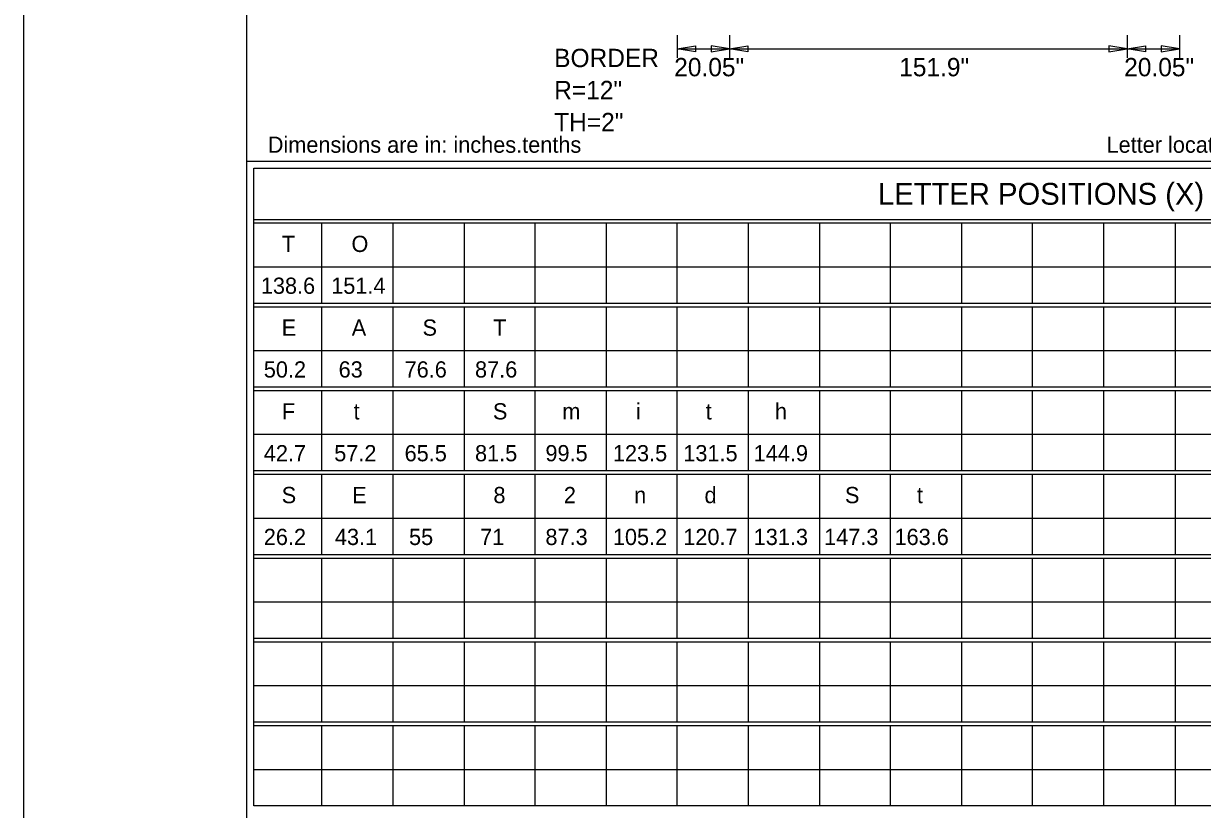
# Model space of a CAD drawing. Extents: x 2150010 to 2150174, y 145114 to 145224.
# Drawn here: x 2150010.46 to 2150048, y 145167.07 to 145192.08 of the extents above; entities that cross this region are included whole.
import ezdxf

# ---------------------------------------------------------------- set-up
doc = ezdxf.new("R2010")
doc.units = 0
for name, color, linetype in [('BORDER', 7, 'Continuous'), ('GSDIMS', 7, 'Continuous'), ('Level 1', 7, 'Continuous'), ('PDF', 7, 'Continuous')]:
    doc.layers.add(name, color=color, linetype=linetype)

msp = doc.modelspace()

# ---------------------------------------------------------------- linework, layer by layer
at = {"layer": 'BORDER'}
for p, q in [((2150010.458, 145219.948), (2150010.458, 145114.088)), ((2150017.557, 145216.512), (2150017.557, 145117.388))]:
    msp.add_line(p, q, dxfattribs=at)
at = {"layer": 'GSDIMS'}
for p, q in [((2150031.27, 145191.716), (2150031.27, 145190.986)), ((2150031.27, 145191.716), (2150031.27, 145190.986)), ((2150032.942, 145191.716), (2150032.942, 145190.986)), ((2150032.942, 145191.716), (2150032.942, 145190.986)), ((2150045.598, 145191.716), (2150045.598, 145190.986)), ((2150045.598, 145191.716), (2150045.598, 145190.986)), ((2150047.27, 145191.716), (2150047.27, 145190.986)), ((2150047.27, 145191.716), (2150047.27, 145190.986)), ((2150031.27, 145191.278), (2150032.942, 145191.278)), ((2150032.942, 145191.278), (2150045.598, 145191.278)), ((2150045.598, 145191.278), (2150047.27, 145191.278))]:
    msp.add_line(p, q, dxfattribs=at)
for points in [[(2150031.27, 145191.278), (2150031.853, 145191.375), (2150031.853, 145191.181)], [(2150032.942, 145191.278), (2150032.358, 145191.375), (2150032.358, 145191.181)], [(2150032.942, 145191.278), (2150033.525, 145191.375), (2150033.525, 145191.181)], [(2150045.598, 145191.278), (2150045.015, 145191.375), (2150045.015, 145191.181)], [(2150045.598, 145191.278), (2150046.182, 145191.375), (2150046.182, 145191.181)], [(2150047.27, 145191.278), (2150046.687, 145191.375), (2150046.687, 145191.181)]]:
    msp.add_lwpolyline(points, close=True, dxfattribs=at)
at = {"layer": 'Level 1'}
for p, q in [((2150017.557, 145187.705), (2150062.583, 145187.705)), ((2150017.789, 145185.849), (2150076.084, 145185.849)), ((2150017.789, 145185.733), (2150076.084, 145185.733)), ((2150019.946, 145185.733), (2150019.946, 145183.183)), ((2150022.218, 145185.733), (2150022.218, 145183.183)), ((2150024.491, 145185.733), (2150024.491, 145183.183)), ((2150026.74, 145185.733), (2150026.74, 145183.183)), ((2150029.013, 145185.733), (2150029.013, 145183.183)), ((2150031.262, 145185.733), (2150031.262, 145183.183)), ((2150033.535, 145185.733), (2150033.535, 145183.183)), ((2150035.808, 145185.733), (2150035.808, 145183.183)), ((2150038.057, 145185.733), (2150038.057, 145183.183)), ((2150040.329, 145185.733), (2150040.329, 145183.183)), ((2150042.579, 145185.733), (2150042.579, 145183.183)), ((2150044.851, 145185.733), (2150044.851, 145183.183)), ((2150047.124, 145185.733), (2150047.124, 145183.183)), ((2150017.789, 145184.342), (2150067.426, 145184.342)), ((2150017.789, 145183.183), (2150076.084, 145183.183)), ((2150017.789, 145183.067), (2150076.084, 145183.067)), ((2150019.946, 145183.067), (2150019.946, 145180.516)), ((2150022.218, 145183.067), (2150022.218, 145180.516)), ((2150024.491, 145183.067), (2150024.491, 145180.516)), ((2150026.74, 145183.067), (2150026.74, 145180.516)), ((2150029.013, 145183.067), (2150029.013, 145180.516)), ((2150031.262, 145183.067), (2150031.262, 145180.516)), ((2150033.535, 145183.067), (2150033.535, 145180.516)), ((2150035.808, 145183.067), (2150035.808, 145180.516)), ((2150038.057, 145183.067), (2150038.057, 145180.516)), ((2150040.329, 145183.067), (2150040.329, 145180.516)), ((2150042.579, 145183.067), (2150042.579, 145180.516)), ((2150044.851, 145183.067), (2150044.851, 145180.516)), ((2150047.124, 145183.067), (2150047.124, 145180.516)), ((2150017.789, 145181.675), (2150067.426, 145181.675)), ((2150017.789, 145180.516), (2150076.084, 145180.516)), ((2150017.789, 145180.4), (2150076.084, 145180.4)), ((2150019.946, 145180.4), (2150019.946, 145177.849)), ((2150022.218, 145180.4), (2150022.218, 145177.849)), ((2150024.491, 145180.4), (2150024.491, 145177.849)), ((2150026.74, 145180.4), (2150026.74, 145177.849)), ((2150029.013, 145180.4), (2150029.013, 145177.849)), ((2150031.262, 145180.4), (2150031.262, 145177.849)), ((2150033.535, 145180.4), (2150033.535, 145177.849)), ((2150035.808, 145180.4), (2150035.808, 145177.849)), ((2150038.057, 145180.4), (2150038.057, 145177.849)), ((2150040.329, 145180.4), (2150040.329, 145177.849)), ((2150042.579, 145180.4), (2150042.579, 145177.849)), ((2150044.851, 145180.4), (2150044.851, 145177.849)), ((2150047.124, 145180.4), (2150047.124, 145177.849)), ((2150017.789, 145179.008), (2150067.426, 145179.008)), ((2150017.789, 145177.849), (2150076.084, 145177.849)), ((2150017.789, 145177.733), (2150076.084, 145177.733)), ((2150019.946, 145177.733), (2150019.946, 145175.182)), ((2150022.218, 145177.733), (2150022.218, 145175.182)), ((2150024.491, 145177.733), (2150024.491, 145175.182)), ((2150026.74, 145177.733), (2150026.74, 145175.182)), ((2150029.013, 145177.733), (2150029.013, 145175.182)), ((2150031.262, 145177.733), (2150031.262, 145175.182)), ((2150033.535, 145177.733), (2150033.535, 145175.182)), ((2150035.808, 145177.733), (2150035.808, 145175.182)), ((2150038.057, 145177.733), (2150038.057, 145175.182)), ((2150040.329, 145177.733), (2150040.329, 145175.182)), ((2150042.579, 145177.733), (2150042.579, 145175.182)), ((2150044.851, 145177.733), (2150044.851, 145175.182)), ((2150047.124, 145177.733), (2150047.124, 145175.182)), ((2150017.789, 145176.342), (2150067.426, 145176.342)), ((2150017.789, 145175.182), (2150076.084, 145175.182)), ((2150017.789, 145175.066), (2150076.084, 145175.066)), ((2150019.946, 145175.066), (2150019.946, 145172.515)), ((2150022.218, 145175.066), (2150022.218, 145172.515)), ((2150024.491, 145175.066), (2150024.491, 145172.515)), ((2150026.74, 145175.066), (2150026.74, 145172.515)), ((2150029.013, 145175.066), (2150029.013, 145172.515)), ((2150031.262, 145175.066), (2150031.262, 145172.515)), ((2150033.535, 145175.066), (2150033.535, 145172.515)), ((2150035.808, 145175.066), (2150035.808, 145172.515)), ((2150038.057, 145175.066), (2150038.057, 145172.515)), ((2150040.329, 145175.066), (2150040.329, 145172.515)), ((2150042.579, 145175.066), (2150042.579, 145172.515)), ((2150044.851, 145175.066), (2150044.851, 145172.515)), ((2150047.124, 145175.066), (2150047.124, 145172.515)), ((2150017.789, 145173.675), (2150067.426, 145173.675)), ((2150017.789, 145172.515), (2150076.084, 145172.515)), ((2150017.789, 145172.399), (2150076.084, 145172.399)), ((2150019.946, 145172.399), (2150019.946, 145169.849)), ((2150022.218, 145172.399), (2150022.218, 145169.849)), ((2150024.491, 145172.399), (2150024.491, 145169.849)), ((2150026.74, 145172.399), (2150026.74, 145169.849)), ((2150029.013, 145172.399), (2150029.013, 145169.849)), ((2150031.262, 145172.399), (2150031.262, 145169.849)), ((2150033.535, 145172.399), (2150033.535, 145169.849)), ((2150035.808, 145172.399), (2150035.808, 145169.849)), ((2150038.057, 145172.399), (2150038.057, 145169.849)), ((2150040.329, 145172.399), (2150040.329, 145169.849)), ((2150042.579, 145172.399), (2150042.579, 145169.849)), ((2150044.851, 145172.399), (2150044.851, 145169.849)), ((2150047.124, 145172.399), (2150047.124, 145169.849)), ((2150017.789, 145171.008), (2150067.426, 145171.008)), ((2150017.789, 145169.849), (2150076.084, 145169.849)), ((2150017.789, 145169.733), (2150076.084, 145169.733)), ((2150019.946, 145169.733), (2150019.946, 145167.182)), ((2150022.218, 145169.733), (2150022.218, 145167.182)), ((2150024.491, 145169.733), (2150024.491, 145167.182)), ((2150026.74, 145169.733), (2150026.74, 145167.182)), ((2150029.013, 145169.733), (2150029.013, 145167.182)), ((2150031.262, 145169.733), (2150031.262, 145167.182)), ((2150033.535, 145169.733), (2150033.535, 145167.182)), ((2150035.808, 145169.733), (2150035.808, 145167.182)), ((2150038.057, 145169.733), (2150038.057, 145167.182)), ((2150040.329, 145169.733), (2150040.329, 145167.182)), ((2150042.579, 145169.733), (2150042.579, 145167.182)), ((2150044.851, 145169.733), (2150044.851, 145167.182)), ((2150047.124, 145169.733), (2150047.124, 145167.182)), ((2150017.789, 145168.341), (2150067.426, 145168.341))]:
    msp.add_line(p, q, dxfattribs=at)
msp.add_lwpolyline([(2150017.789, 145187.473), (2150076.084, 145187.473), (2150076.084, 145167.182), (2150017.789, 145167.182)], close=True, dxfattribs=at)
at = {"layer": 'PDF'}
msp.add_lwpolyline([(2150010.458, 145114.088), (2150174.061, 145114.088), (2150174.061, 145219.948), (2150010.458, 145219.948)], close=True, dxfattribs=at)

# ---------------------------------------------------------------- texts
at = {"layer": 'GSDIMS'}
for s, p in [('BORDER', (2150027.354, 145190.695)), ('20.05"', (2150031.177, 145190.403)), ('151.9"', (2150038.341, 145190.403)), ('20.05"', (2150045.505, 145190.403)), ('R=12"', (2150027.354, 145189.674)), ('TH=2"', (2150027.354, 145188.653))]:
    msp.add_text(s, height=0.5833, dxfattribs=at).set_placement(p)
at = {"layer": 'Level 1'}
for s, height, p in [('Dimensions are in: inches.tenths', 0.51652, (2150018.235, 145187.968)), ('Letter locations are panel edge to lower left corner', 0.51652, (2150044.943, 145187.968)), ('LETTER POSITIONS (X)', 0.69555, (2150037.664, 145186.313)), ('T', 0.517, (2150018.683, 145184.81)), ('O', 0.517, (2150020.899, 145184.81)), ('138.6', 0.5165, (2150018.014, 145183.478)), ('151.4', 0.5165, (2150020.254, 145183.478)), ('E', 0.517, (2150018.678, 145182.145)), ('A', 0.517, (2150020.908, 145182.145)), ('S', 0.517, (2150023.162, 145182.145)), ('T', 0.517, (2150025.409, 145182.145)), ('50.2', 0.5165, (2150018.108, 145180.812)), ('63', 0.5165, (2150020.491, 145180.813)), ('76.6', 0.5165, (2150022.592, 145180.813)), ('87.6', 0.5165, (2150024.834, 145180.813)), ('F', 0.517, (2150018.687, 145179.479)), ('t', 0.517, (2150020.967, 145179.479)), ('S', 0.517, (2150025.404, 145179.479)), ('m', 0.517, (2150027.613, 145179.479)), ('i', 0.517, (2150029.956, 145179.479)), ('t', 0.517, (2150032.177, 145179.479)), ('h', 0.517, (2150034.383, 145179.479)), ('42.7', 0.5165, (2150018.108, 145178.147)), ('57.2', 0.5165, (2150020.35, 145178.147)), ('65.5', 0.5165, (2150022.592, 145178.147)), ('81.5', 0.5165, (2150024.834, 145178.147)), ('99.5', 0.5165, (2150027.076, 145178.147)), ('123.5', 0.5165, (2150029.224, 145178.147)), ('131.5', 0.5165, (2150031.466, 145178.147)), ('144.9', 0.5165, (2150033.708, 145178.147)), ('S', 0.517, (2150018.678, 145176.814)), ('E', 0.517, (2150020.92, 145176.814)), ('8', 0.517, (2150025.42, 145176.814)), ('2', 0.517, (2150027.662, 145176.814)), ('n', 0.517, (2150029.9, 145176.814)), ('d', 0.517, (2150032.142, 145176.814)), ('S', 0.517, (2150036.614, 145176.814)), ('t', 0.517, (2150038.903, 145176.814)), ('26.2', 0.5165, (2150018.108, 145175.482)), ('43.1', 0.5165, (2150020.372, 145175.482)), ('55', 0.5165, (2150022.733, 145175.482)), ('71', 0.5165, (2150024.996, 145175.482)), ('87.3', 0.5165, (2150027.076, 145175.482)), ('105.2', 0.5165, (2150029.224, 145175.482)), ('120.7', 0.5165, (2150031.466, 145175.482)), ('131.3', 0.5165, (2150033.708, 145175.482)), ('147.3', 0.5165, (2150035.95, 145175.482)), ('163.6', 0.5165, (2150038.192, 145175.482))]:
    msp.add_text(s, height=height, dxfattribs=at).set_placement(p)

doc.saveas('drawing.dxf')
